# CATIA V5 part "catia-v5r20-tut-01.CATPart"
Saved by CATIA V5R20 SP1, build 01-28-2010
Part number: Part1
Bounding box of the stored display mesh (mm): x 0 to 0, y -100 to 100, z -100 to 100
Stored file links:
  D:\v5_r20\psrt_files_downloaded\c03-catia-v5r20-prt\catia-v5r20-tut-01.CATPart
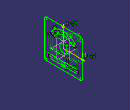
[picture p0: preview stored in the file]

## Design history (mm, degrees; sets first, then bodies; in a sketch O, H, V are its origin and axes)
Body1 (main body)
  Sketch1 on yz-plane, origin (0, 0, 0), H (0, 1, 0), V (0, 0, 1)
    line L1 (100, 90) -> (100, -90)
    line L2 (90, -100) -> (-90, -100)
    line L3 (-100, -90) -> (-100, 90)
    line L4 (-90, 100) -> (90, 100)
    construction line L5 (-70, -70) -> (70, -70)
    line L6 (-70, -60) -> (70, -60)
    line L7 (70, -80) -> (-70, -80)
    arc A1 centre (70, -70) radius 10 from (70, -60) to (70, -80) cw
    arc A2 centre (-70, -70) radius 10 from (-70, -80) to (-70, -60) cw
    point P3 (-70, -60)
    point P4 (70, -60)
    construction arc A3 centre (0, 0) radius 70 from (57.4456, 40) to (-57.4456, 40) ccw
    arc A4 centre (57.4456, 40) radius 10 from (65.6521, 45.7143) to (49.2391, 34.2857) cw
    arc A5 centre (-57.4456, 40) radius 10 from (-49.2391, 34.2857) to (-65.6521, 45.7143) cw
    arc A6 centre (0, 0) radius 60 from (49.2391, 34.2857) to (-49.2391, 34.2857) ccw
    arc A7 centre (0, 0) radius 80 from (-65.6521, 45.7143) to (65.6521, 45.7143) cw
    circle A8 centre (0, 0) radius 20
    arc A9 centre (90, 90) radius 10 from (100, 90) to (90, 100) ccw
    arc A10 centre (-90, 90) radius 10 from (-100, 90) to (-90, 100) cw
    arc A11 centre (-90, -90) radius 10 from (-90, -100) to (-100, -90) cw
    arc A12 centre (90, -90) radius 10 from (100, -90) to (90, -100) cw
    reference intersected line E1 through (0, 0) direction (-1, 0) from xy-plane
    reference intersected line E3 through (0, 0) direction (0, 1) from zx-plane
    radius A5 = 10
    radius A9 = 10
    radius A10 = 10
    radius A12 = 10
    radius A7 = 80
    radius A8 = 20
    distance V L1 = 100
    distance P3 P4 = 140
    vertical: L1 V, L3 V, E3 V
    horizontal: L2 H, L4 H, L5 H, L7 H, L6 H, E1 H
    equidistance: L1 L3 O, L2 L4 O
    tangency: A1 L6, A2 L6, A1 L7, A2 L7, A3 L5, A6 A5, A5 A7, A7 A4, A4 A6, A9 L1, A9 L4, A10 L3, A10 L4, A11 L2, A11 L3, A12 L1, A12 L2, L6 A6, L7 A7, L7 A11, L7 A12
    parallelism: L5 L6
    concentricity: A6 O, A7 O
    perpendicularity: E1 L1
